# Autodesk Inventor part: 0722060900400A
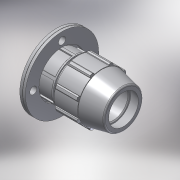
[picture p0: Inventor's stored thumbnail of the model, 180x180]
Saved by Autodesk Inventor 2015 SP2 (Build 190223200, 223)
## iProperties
Created: 2017-02
Part Number: 0722060900400A
Material: PVC-Piping
Description: PLASSON COMPRESSION FLANGE ADAPTOR 90-4"
Document SubType Name: Modeling
Designer: KIM
Mass: 92.6774 g
Surface Area: 199.44 cm^2
Volume: 66.1981 cm^3
Density: 1.4 g/cm^3
Appearance: Smooth - White
Author: KIM
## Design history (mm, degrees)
derived "87220.ipt"
feature "Solid1::87220.ipt"
tag "TaggingFeature1"
body "Solid1"
other parameters: "d4" = 27.85714, "d5" = 62.4, "d7" = 154, "d9" = 27.85714, "d11" = 5.57143, "d12" = 123.2, "d13" = 120 deg, "d14" = 117, "d15" = 12 deg, "d18" = 4.5, "d19" = 35 deg, "d20" = 17.5 deg, "d21" = 143.22, "d23" = 0, "d25" = 360 deg, "d27" = 3.08, "d34" = 7.7, "d36" = 0, "d42" = 68.25, "d43" = 4.62, "d46" = 2.7, "d53" = 1.8, "d55" = 360 deg, "d70" = 195, "d73" = 16.25, "d74" = 90 deg, "d75" = 0.3, "d77" = 18, "d80" = 0, "d82" = 360 deg, "d85" = 130.9, "d86" = 123.2, "d87" = 2.75, "d88" = 0.3, "d93" = 9.75, "d94" = 183, "d95" = 81, "E_" = 154, "H_" = 195, "l_" = 183, "S_" = 18
